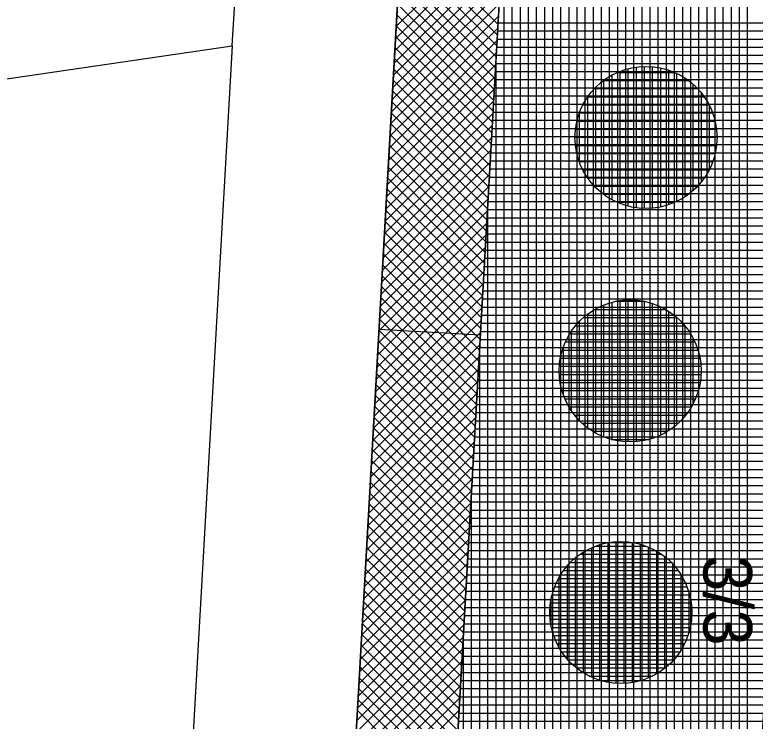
# Model space of a CAD drawing. Extents: x -565346 to -564154, y -1097386 to -1095620.
# Drawn here: x -564297.25 to -564279, y -1097000.39 to -1096982.99 of the extents above; entities that cross this region are included whole.
import ezdxf

# ---------------------------------------------------------------- set-up
doc = ezdxf.new("R2010")
doc.units = 0
for name, color, linetype in [('Vrstva 1', 7, 'Continuous'), ('Vrstva 40', 7, 'Continuous'), ('Vrstva 41', 7, 'Continuous'), ('Vrstva 42', 7, 'Continuous'), ('Vrstva 43', 7, 'Continuous'), ('Vrstva 44', 7, 'Continuous')]:
    doc.layers.add(name, color=color, linetype=linetype)

msp = doc.modelspace()

# ---------------------------------------------------------------- linework, layer by layer
at = {"layer": 'Vrstva 1'}
for p, q in [((-564296.5, -1097135.53), (-564285.9, -1096948.97)), ((-564291.89, -1096983.76), (-564290.54, -1096959.99)), ((-564455.988, -1097007.624), (-564291.89, -1096983.76)), ((-564291.89, -1096983.76), (-564296.48, -1097064.53))]:
    msp.add_line(p, q, dxfattribs=at)
at = {"layer": 'Vrstva 41'}
msp.add_line((-564288.277, -1096990.734), (-564285.782, -1096990.875), dxfattribs=at)
msp.add_lwpolyline([(-564296.782, -1097140.492), (-564294.286, -1097140.634), (-564282.373, -1096930.972), (-564284.87, -1096930.83)], close=True, dxfattribs=at)
at = {"layer": 'Vrstva 42'}
for p, q in [((-564285.194, -1096980.625), (-564287.85, -1096983.281)), ((-564285.211, -1096980.925), (-564287.867, -1096983.581)), ((-564287.712, -1096980.855), (-564285.342, -1096983.225)), ((-564287.728, -1096981.122), (-564285.357, -1096983.493)), ((-564285.228, -1096981.225), (-564287.884, -1096983.881)), ((-564285.245, -1096981.525), (-564287.901, -1096984.181)), ((-564287.743, -1096981.39), (-564285.372, -1096983.76)), ((-564287.758, -1096981.658), (-564285.388, -1096984.028)), ((-564285.262, -1096981.825), (-564287.918, -1096984.48)), ((-564287.773, -1096981.925), (-564285.403, -1096984.296)), ((-564285.279, -1096982.125), (-564287.935, -1096984.78)), ((-564287.788, -1096982.193), (-564285.418, -1096984.563)), ((-564285.297, -1096982.424), (-564287.952, -1096985.08)), ((-564287.804, -1096982.461), (-564285.433, -1096984.831)), ((-564285.314, -1096982.724), (-564287.969, -1096985.38)), ((-564287.819, -1096982.728), (-564285.448, -1096985.099)), ((-564287.834, -1096982.996), (-564285.464, -1096985.366)), ((-564285.331, -1096983.024), (-564287.986, -1096985.68)), ((-564285.348, -1096983.324), (-564288.003, -1096985.98)), ((-564287.849, -1096983.264), (-564285.479, -1096985.634)), ((-564287.864, -1096983.531), (-564285.494, -1096985.902)), ((-564285.365, -1096983.624), (-564288.021, -1096986.28)), ((-564287.88, -1096983.799), (-564285.509, -1096986.169)), ((-564285.382, -1096983.924), (-564288.038, -1096986.58)), ((-564287.895, -1096984.067), (-564285.525, -1096986.437)), ((-564285.399, -1096984.224), (-564288.055, -1096986.88)), ((-564287.91, -1096984.334), (-564285.54, -1096986.704)), ((-564285.416, -1096984.524), (-564288.072, -1096987.179)), ((-564287.925, -1096984.602), (-564285.555, -1096986.972)), ((-564285.433, -1096984.823), (-564288.089, -1096987.479)), ((-564287.94, -1096984.869), (-564285.57, -1096987.24)), ((-564285.45, -1096985.123), (-564288.106, -1096987.779)), ((-564287.956, -1096985.137), (-564285.585, -1096987.507)), ((-564285.467, -1096985.423), (-564288.123, -1096988.079)), ((-564287.971, -1096985.405), (-564285.601, -1096987.775)), ((-564285.484, -1096985.723), (-564288.14, -1096988.379)), ((-564287.986, -1096985.672), (-564285.616, -1096988.043)), ((-564285.501, -1096986.023), (-564288.157, -1096988.679)), ((-564288.001, -1096985.94), (-564285.631, -1096988.31)), ((-564288.016, -1096986.208), (-564285.646, -1096988.578)), ((-564285.518, -1096986.323), (-564288.174, -1096988.979)), ((-564285.535, -1096986.623), (-564288.191, -1096989.279)), ((-564288.032, -1096986.475), (-564285.661, -1096988.845)), ((-564288.047, -1096986.743), (-564285.677, -1096989.113)), ((-564285.552, -1096986.923), (-564288.208, -1096989.578)), ((-564288.062, -1096987.011), (-564285.692, -1096989.381)), ((-564285.569, -1096987.223), (-564288.225, -1096989.878)), ((-564288.077, -1096987.278), (-564285.707, -1096989.648)), ((-564285.586, -1096987.522), (-564288.242, -1096990.178)), ((-564288.092, -1096987.546), (-564285.722, -1096989.916)), ((-564285.603, -1096987.822), (-564288.259, -1096990.478)), ((-564288.108, -1096987.813), (-564285.737, -1096990.184)), ((-564288.123, -1096988.081), (-564285.753, -1096990.451)), ((-564285.62, -1096988.122), (-564288.276, -1096990.778)), ((-564285.637, -1096988.422), (-564288.293, -1096991.078)), ((-564288.138, -1096988.349), (-564285.768, -1096990.719)), ((-564288.153, -1096988.616), (-564285.783, -1096990.987)), ((-564285.654, -1096988.722), (-564288.31, -1096991.378)), ((-564285.671, -1096989.022), (-564288.327, -1096991.678)), ((-564288.168, -1096988.884), (-564285.798, -1096991.254)), ((-564288.184, -1096989.152), (-564285.813, -1096991.522)), ((-564285.688, -1096989.322), (-564288.344, -1096991.977)), ((-564288.199, -1096989.419), (-564285.829, -1096991.789)), ((-564285.705, -1096989.622), (-564288.361, -1096992.277)), ((-564288.214, -1096989.687), (-564285.844, -1096992.057)), ((-564285.723, -1096989.921), (-564288.378, -1096992.577)), ((-564288.229, -1096989.955), (-564285.859, -1096992.325)), ((-564285.74, -1096990.221), (-564288.395, -1096992.877)), ((-564288.244, -1096990.222), (-564285.874, -1096992.592)), ((-564285.757, -1096990.521), (-564288.412, -1096993.177)), ((-564288.26, -1096990.49), (-564285.889, -1096992.86)), ((-564285.774, -1096990.821), (-564288.429, -1096993.477)), ((-564288.275, -1096990.757), (-564285.905, -1096993.128)), ((-564288.29, -1096991.025), (-564285.92, -1096993.395)), ((-564285.791, -1096991.121), (-564288.446, -1096993.777)), ((-564288.305, -1096991.293), (-564285.935, -1096993.663)), ((-564285.808, -1096991.421), (-564288.463, -1096994.077)), ((-564288.321, -1096991.56), (-564285.95, -1096993.931)), ((-564285.825, -1096991.721), (-564288.481, -1096994.377)), ((-564288.336, -1096991.828), (-564285.966, -1096994.198)), ((-564285.842, -1096992.021), (-564288.498, -1096994.676)), ((-564288.351, -1096992.096), (-564285.981, -1096994.466)), ((-564285.859, -1096992.321), (-564288.515, -1096994.976)), ((-564288.366, -1096992.363), (-564285.996, -1096994.733)), ((-564285.876, -1096992.62), (-564288.532, -1096995.276)), ((-564288.381, -1096992.631), (-564286.011, -1096995.001)), ((-564285.893, -1096992.92), (-564288.549, -1096995.576)), ((-564288.397, -1096992.899), (-564286.026, -1096995.269)), ((-564288.412, -1096993.166), (-564286.042, -1096995.536)), ((-564285.91, -1096993.22), (-564288.566, -1096995.876)), ((-564285.927, -1096993.52), (-564288.583, -1096996.176)), ((-564288.427, -1096993.434), (-564286.057, -1096995.804)), ((-564288.442, -1096993.701), (-564286.072, -1096996.072)), ((-564285.944, -1096993.82), (-564288.6, -1096996.476)), ((-564285.961, -1096994.12), (-564288.617, -1096996.776)), ((-564288.457, -1096993.969), (-564286.087, -1096996.339)), ((-564288.473, -1096994.237), (-564286.102, -1096996.607)), ((-564285.978, -1096994.42), (-564288.634, -1096997.075)), ((-564288.488, -1096994.504), (-564286.118, -1096996.875)), ((-564285.995, -1096994.72), (-564288.651, -1096997.375)), ((-564288.503, -1096994.772), (-564286.133, -1096997.142)), ((-564286.012, -1096995.019), (-564288.668, -1096997.675)), ((-564288.518, -1096995.04), (-564286.148, -1096997.41)), ((-564286.029, -1096995.319), (-564288.685, -1096997.975)), ((-564288.533, -1096995.307), (-564286.163, -1096997.677)), ((-564288.549, -1096995.575), (-564286.178, -1096997.945)), ((-564286.046, -1096995.619), (-564288.702, -1096998.275)), ((-564286.063, -1096995.919), (-564288.719, -1096998.575)), ((-564288.564, -1096995.843), (-564286.194, -1096998.213)), ((-564288.579, -1096996.11), (-564286.209, -1096998.48)), ((-564286.08, -1096996.219), (-564288.736, -1096998.875)), ((-564288.594, -1096996.378), (-564286.224, -1096998.748)), ((-564286.097, -1096996.519), (-564288.753, -1096999.175)), ((-564288.609, -1096996.645), (-564286.239, -1096999.016)), ((-564286.114, -1096996.819), (-564288.77, -1096999.474)), ((-564288.625, -1096996.913), (-564286.254, -1096999.283)), ((-564286.131, -1096997.119), (-564288.787, -1096999.774)), ((-564288.64, -1096997.181), (-564286.27, -1096999.551)), ((-564286.148, -1096997.419), (-564288.804, -1097000.074)), ((-564288.655, -1096997.448), (-564286.285, -1096999.819)), ((-564286.166, -1096997.718), (-564288.821, -1097000.374)), ((-564288.67, -1096997.716), (-564286.3, -1097000.086)), ((-564286.183, -1096998.018), (-564288.838, -1097000.674)), ((-564288.685, -1096997.984), (-564286.315, -1097000.354)), ((-564286.2, -1096998.318), (-564288.855, -1097000.974)), ((-564288.701, -1096998.251), (-564286.33, -1097000.621)), ((-564286.217, -1096998.618), (-564288.872, -1097001.274)), ((-564288.716, -1096998.519), (-564286.346, -1097000.889)), ((-564288.731, -1096998.787), (-564286.361, -1097001.157)), ((-564286.234, -1096998.918), (-564288.889, -1097001.574)), ((-564288.746, -1096999.054), (-564286.376, -1097001.424)), ((-564286.251, -1096999.218), (-564288.906, -1097001.874)), ((-564288.761, -1096999.322), (-564286.391, -1097001.692)), ((-564286.268, -1096999.518), (-564288.923, -1097002.173)), ((-564288.777, -1096999.589), (-564286.407, -1097001.96)), ((-564286.285, -1096999.818), (-564288.941, -1097002.473)), ((-564288.792, -1096999.857), (-564286.422, -1097002.227)), ((-564286.302, -1097000.117), (-564288.958, -1097002.773)), ((-564288.807, -1097000.125), (-564286.437, -1097002.495))]:
    msp.add_line(p, q, dxfattribs=at)
at = {"layer": 'Vrstva 43'}
for p, q in [((-564279.19, -1097007.173), (-564279.19, -1096883.64)), ((-564279.39, -1097010.696), (-564279.39, -1096887.165)), ((-564279.59, -1097014.219), (-564279.59, -1096890.689)), ((-564279.79, -1097017.742), (-564279.79, -1096894.214)), ((-564279.99, -1097021.265), (-564279.99, -1096897.739)), ((-564280.19, -1097024.788), (-564280.19, -1096901.264)), ((-564280.39, -1097028.31), (-564280.39, -1096904.789)), ((-564282.19, -1097060.016), (-564282.19, -1096906.123)), ((-564281.99, -1097056.493), (-564281.99, -1096906.114)), ((-564281.79, -1097052.97), (-564281.79, -1096906.104)), ((-564281.59, -1097049.447), (-564281.59, -1096906.094)), ((-564281.39, -1097045.925), (-564281.39, -1096906.085)), ((-564281.19, -1097042.402), (-564281.19, -1096906.075)), ((-564280.99, -1097038.879), (-564280.99, -1096906.065)), ((-564280.79, -1097035.356), (-564280.79, -1096906.056)), ((-564280.59, -1097031.833), (-564280.59, -1096906.046)), ((-564282.39, -1097063.539), (-564282.39, -1096931.271)), ((-564282.59, -1097067.062), (-564282.59, -1096934.791)), ((-564282.79, -1097070.585), (-564282.79, -1096938.311)), ((-564282.99, -1097074.107), (-564282.99, -1096941.831)), ((-564283.19, -1097077.63), (-564283.19, -1096945.351)), ((-564283.39, -1097081.153), (-564283.39, -1096948.871)), ((-564283.59, -1097084.676), (-564283.59, -1096952.391)), ((-564283.79, -1097088.199), (-564283.79, -1096955.91)), ((-564283.99, -1097091.722), (-564283.99, -1096959.43)), ((-564284.19, -1097095.244), (-564284.19, -1096962.95)), ((-564284.39, -1097098.767), (-564284.39, -1096966.47)), ((-564284.59, -1097102.29), (-564284.59, -1096969.99)), ((-564284.79, -1097105.813), (-564284.79, -1096973.51)), ((-564284.99, -1097109.336), (-564284.99, -1096977.03)), ((-564285.19, -1097112.859), (-564285.19, -1096980.55)), ((-564285.34, -1096983.19), (-564277.828, -1096983.19)), ((-564285.351, -1096983.39), (-564277.84, -1096983.39)), ((-564285.363, -1096983.59), (-564277.851, -1096983.59)), ((-564285.374, -1096983.79), (-564277.862, -1096983.79)), ((-564285.39, -1097116.382), (-564285.39, -1096984.069)), ((-564285.385, -1096983.99), (-564277.874, -1096983.99)), ((-564285.397, -1096984.19), (-564277.885, -1096984.19)), ((-564285.408, -1096984.39), (-564277.897, -1096984.39)), ((-564285.42, -1096984.59), (-564277.908, -1096984.59)), ((-564285.431, -1096984.79), (-564277.919, -1096984.79)), ((-564285.442, -1096984.99), (-564277.931, -1096984.99)), ((-564285.454, -1096985.19), (-564277.942, -1096985.19)), ((-564285.465, -1096985.39), (-564277.953, -1096985.39)), ((-564285.476, -1096985.59), (-564277.965, -1096985.59)), ((-564285.488, -1096985.79), (-564277.976, -1096985.79)), ((-564285.499, -1096985.99), (-564277.987, -1096985.99)), ((-564285.51, -1096986.19), (-564277.999, -1096986.19)), ((-564285.522, -1096986.39), (-564278.01, -1096986.39)), ((-564285.533, -1096986.59), (-564278.021, -1096986.59)), ((-564285.545, -1096986.79), (-564278.033, -1096986.79)), ((-564285.556, -1096986.99), (-564278.044, -1096986.99)), ((-564285.567, -1096987.19), (-564278.055, -1096987.19)), ((-564285.579, -1096987.39), (-564278.067, -1096987.39)), ((-564285.59, -1097119.904), (-564285.59, -1096987.589)), ((-564285.59, -1096987.59), (-564278.078, -1096987.59)), ((-564285.601, -1096987.79), (-564278.09, -1096987.79)), ((-564285.613, -1096987.99), (-564278.101, -1096987.99)), ((-564285.624, -1096988.19), (-564278.112, -1096988.19)), ((-564285.635, -1096988.39), (-564278.124, -1096988.39)), ((-564285.647, -1096988.59), (-564278.135, -1096988.59)), ((-564285.658, -1096988.79), (-564278.146, -1096988.79)), ((-564285.67, -1096988.99), (-564278.158, -1096988.99)), ((-564285.681, -1096989.19), (-564278.169, -1096989.19)), ((-564285.692, -1096989.39), (-564278.18, -1096989.39)), ((-564285.704, -1096989.59), (-564278.192, -1096989.59)), ((-564285.715, -1096989.79), (-564278.203, -1096989.79)), ((-564285.726, -1096989.99), (-564278.214, -1096989.99)), ((-564285.738, -1096990.19), (-564278.226, -1096990.19)), ((-564285.749, -1096990.39), (-564278.237, -1096990.39)), ((-564285.76, -1096990.59), (-564278.249, -1096990.59)), ((-564285.772, -1096990.79), (-564278.26, -1096990.79)), ((-564285.783, -1096990.99), (-564278.271, -1096990.99)), ((-564285.795, -1096991.19), (-564278.283, -1096991.19)), ((-564285.79, -1097123.427), (-564285.79, -1096991.109)), ((-564285.806, -1096991.39), (-564278.294, -1096991.39)), ((-564285.817, -1096991.59), (-564278.305, -1096991.59)), ((-564285.829, -1096991.79), (-564278.317, -1096991.79)), ((-564285.84, -1096991.99), (-564278.328, -1096991.99)), ((-564285.851, -1096992.19), (-564278.339, -1096992.19)), ((-564285.863, -1096992.39), (-564278.351, -1096992.39)), ((-564285.874, -1096992.59), (-564278.362, -1096992.59)), ((-564285.885, -1096992.79), (-564278.373, -1096992.79)), ((-564285.897, -1096992.99), (-564278.385, -1096992.99)), ((-564285.908, -1096993.19), (-564278.396, -1096993.19)), ((-564285.92, -1096993.39), (-564278.407, -1096993.39)), ((-564285.931, -1096993.59), (-564278.419, -1096993.59)), ((-564285.942, -1096993.79), (-564278.43, -1096993.79)), ((-564285.954, -1096993.99), (-564278.442, -1096993.99)), ((-564285.965, -1096994.19), (-564278.453, -1096994.19)), ((-564285.976, -1096994.39), (-564278.464, -1096994.39)), ((-564285.99, -1097126.95), (-564285.99, -1096994.629)), ((-564285.988, -1096994.59), (-564278.476, -1096994.59)), ((-564285.999, -1096994.79), (-564278.487, -1096994.79)), ((-564286.011, -1096994.99), (-564278.498, -1096994.99)), ((-564286.022, -1096995.19), (-564278.51, -1096995.19)), ((-564286.033, -1096995.39), (-564278.521, -1096995.39)), ((-564286.045, -1096995.59), (-564278.532, -1096995.59)), ((-564286.056, -1096995.79), (-564278.544, -1096995.79)), ((-564286.067, -1096995.99), (-564278.555, -1096995.99)), ((-564286.079, -1096996.19), (-564278.566, -1096996.19)), ((-564286.09, -1096996.39), (-564278.578, -1096996.39)), ((-564286.101, -1096996.59), (-564278.589, -1096996.59)), ((-564286.113, -1096996.79), (-564278.601, -1096996.79)), ((-564286.124, -1096996.99), (-564278.612, -1096996.99)), ((-564286.136, -1096997.19), (-564278.623, -1096997.19)), ((-564286.147, -1096997.39), (-564278.635, -1096997.39)), ((-564286.158, -1096997.59), (-564278.646, -1096997.59)), ((-564286.17, -1096997.79), (-564278.657, -1096997.79)), ((-564286.181, -1096997.99), (-564278.669, -1096997.99)), ((-564286.192, -1096998.19), (-564278.68, -1096998.19)), ((-564286.19, -1097130.473), (-564286.19, -1096998.149)), ((-564286.204, -1096998.39), (-564278.691, -1096998.39)), ((-564286.215, -1096998.59), (-564278.703, -1096998.59)), ((-564286.226, -1096998.79), (-564278.714, -1096998.79)), ((-564286.238, -1096998.99), (-564278.725, -1096998.99)), ((-564286.249, -1096999.19), (-564278.737, -1096999.19)), ((-564286.261, -1096999.39), (-564278.748, -1096999.39)), ((-564286.272, -1096999.59), (-564278.759, -1096999.59)), ((-564286.283, -1096999.79), (-564278.771, -1096999.79)), ((-564286.295, -1096999.99), (-564278.782, -1096999.99)), ((-564286.306, -1097000.19), (-564278.794, -1097000.19)), ((-564286.317, -1097000.39), (-564278.805, -1097000.39))]:
    msp.add_line(p, q, dxfattribs=at)
msp.add_lwpolyline([(-564283.37, -1096906.18), (-564284.87, -1096930.83), (-564282.373, -1096930.972), (-564294.286, -1097140.634), (-564296.782, -1097140.492), (-564297.42, -1097150.37), (-564294.347, -1097150.646), (-564303.226, -1097307.04), (-564304.096, -1097322.37), (-564304.399, -1097332.838), (-564302.848, -1097333.175), (-564297.082, -1097322.329), (-564293.197, -1097253.877), (-564289.027, -1097180.417), (-564287.358, -1097151.043), (-564285.364, -1097151.156), (-564284.798, -1097141.172), (-564286.791, -1097141.059), (-564274.888, -1096931.397), (-564272.899, -1096931.51), (-564271.475, -1096906.55)], dxfattribs=at)
at = {"layer": 'Vrstva 44'}
for p, q in [((-564281.73, -1096987.763), (-564281.73, -1096984.266)), ((-564281.53, -1096987.755), (-564281.53, -1096984.273)), ((-564282.389, -1096984.41), (-564280.997, -1096984.41)), ((-564282.33, -1096987.644), (-564282.33, -1096984.384)), ((-564282.13, -1096987.708), (-564282.13, -1096984.321)), ((-564281.93, -1096987.747), (-564281.93, -1096984.282)), ((-564281.33, -1096987.724), (-564281.33, -1096984.303)), ((-564281.13, -1096987.669), (-564281.13, -1096984.359)), ((-564280.93, -1096987.588), (-564280.93, -1096984.442)), ((-564282.737, -1096984.61), (-564280.653, -1096984.61)), ((-564282.73, -1096987.422), (-564282.73, -1096984.605)), ((-564282.53, -1096987.55), (-564282.53, -1096984.479)), ((-564280.73, -1096987.472), (-564280.73, -1096984.554)), ((-564282.962, -1096984.81), (-564280.427, -1096984.81)), ((-564282.93, -1096987.251), (-564282.93, -1096984.778)), ((-564280.53, -1096987.32), (-564280.53, -1096984.71)), ((-564280.33, -1096987.107), (-564280.33, -1096984.92)), ((-564283.13, -1096987.014), (-564283.13, -1096985.016)), ((-564283.126, -1096985.01), (-564280.262, -1096985.01)), ((-564283.246, -1096985.21), (-564280.142, -1096985.21)), ((-564280.13, -1096986.797), (-564280.13, -1096985.234)), ((-564283.336, -1096985.41), (-564280.054, -1096985.41)), ((-564283.33, -1096986.631), (-564283.33, -1096985.396)), ((-564283.396, -1096985.61), (-564279.993, -1096985.61)), ((-564283.43, -1096985.81), (-564279.957, -1096985.81)), ((-564283.442, -1096986.01), (-564279.946, -1096986.01)), ((-564283.432, -1096986.21), (-564279.957, -1096986.21)), ((-564283.398, -1096986.41), (-564279.991, -1096986.41)), ((-564283.338, -1096986.61), (-564280.049, -1096986.61)), ((-564283.25, -1096986.81), (-564280.137, -1096986.81)), ((-564283.132, -1096987.01), (-564280.258, -1096987.01)), ((-564282.969, -1096987.21), (-564280.418, -1096987.21)), ((-564282.747, -1096987.41), (-564280.64, -1096987.41)), ((-564282.407, -1096987.61), (-564280.98, -1096987.61)), ((-564282.53, -1096993.455), (-564282.53, -1096990.073)), ((-564282.43, -1096990.05), (-564281.732, -1096990.05)), ((-564282.33, -1096993.495), (-564282.33, -1096990.033)), ((-564282.13, -1096993.513), (-564282.13, -1096990.017)), ((-564281.93, -1096993.506), (-564281.93, -1096990.022)), ((-564281.73, -1096993.476), (-564281.73, -1096990.05)), ((-564281.53, -1096993.422), (-564281.53, -1096990.106)), ((-564282.958, -1096990.25), (-564281.21, -1096990.25)), ((-564282.93, -1096993.294), (-564282.93, -1096990.234)), ((-564282.73, -1096993.39), (-564282.73, -1096990.138)), ((-564281.33, -1096993.343), (-564281.33, -1096990.187)), ((-564281.13, -1096993.229), (-564281.13, -1096990.298)), ((-564283.237, -1096990.45), (-564280.931, -1096990.45)), ((-564283.13, -1096993.165), (-564283.13, -1096990.362)), ((-564280.93, -1096993.078), (-564280.93, -1096990.451)), ((-564283.431, -1096990.65), (-564280.735, -1096990.65)), ((-564283.33, -1096992.991), (-564283.33, -1096990.538)), ((-564280.73, -1096992.869), (-564280.73, -1096990.657)), ((-564283.53, -1096992.748), (-564283.53, -1096990.781)), ((-564283.575, -1096990.85), (-564280.594, -1096990.85)), ((-564280.53, -1096992.565), (-564280.53, -1096990.963)), ((-564283.73, -1096992.355), (-564283.73, -1096991.17)), ((-564283.681, -1096991.05), (-564280.487, -1096991.05)), ((-564283.755, -1096991.25), (-564280.412, -1096991.25)), ((-564283.804, -1096991.45), (-564280.365, -1096991.45)), ((-564283.83, -1096991.65), (-564280.34, -1096991.65)), ((-564283.831, -1096991.85), (-564280.338, -1096991.85)), ((-564283.809, -1096992.05), (-564280.358, -1096992.05)), ((-564283.763, -1096992.25), (-564280.404, -1096992.25)), ((-564283.693, -1096992.45), (-564280.476, -1096992.45)), ((-564283.592, -1096992.65), (-564280.576, -1096992.65)), ((-564283.454, -1096992.85), (-564280.714, -1096992.85)), ((-564283.269, -1096993.05), (-564280.898, -1096993.05)), ((-564283.006, -1096993.25), (-564281.161, -1096993.25)), ((-564282.55, -1096993.45), (-564281.618, -1096993.45)), ((-564283.03, -1096999.309), (-564283.03, -1096996.119)), ((-564282.94, -1096996.08), (-564281.693, -1096996.08)), ((-564282.83, -1096999.385), (-564282.83, -1096996.043)), ((-564282.63, -1096999.433), (-564282.63, -1096995.993)), ((-564282.43, -1096999.458), (-564282.43, -1096995.969)), ((-564282.23, -1096999.461), (-564282.23, -1096995.968)), ((-564282.03, -1096999.441), (-564282.03, -1096995.989)), ((-564281.83, -1096999.394), (-564281.83, -1096996.034)), ((-564281.63, -1096999.323), (-564281.63, -1096996.104)), ((-564283.314, -1096996.28), (-564281.314, -1096996.28)), ((-564283.23, -1096999.204), (-564283.23, -1096996.224)), ((-564281.43, -1096999.223), (-564281.43, -1096996.206)), ((-564283.552, -1096996.48), (-564281.074, -1096996.48)), ((-564283.43, -1096999.06), (-564283.43, -1096996.368)), ((-564281.23, -1096999.086), (-564281.23, -1096996.342)), ((-564283.726, -1096996.68), (-564280.905, -1096996.68)), ((-564283.63, -1096998.867), (-564283.63, -1096996.561)), ((-564281.03, -1096998.902), (-564281.03, -1096996.528)), ((-564283.83, -1096998.588), (-564283.83, -1096996.841)), ((-564280.83, -1096998.64), (-564280.83, -1096996.791)), ((-564283.851, -1096996.88), (-564280.776, -1096996.88)), ((-564283.943, -1096997.08), (-564280.685, -1096997.08)), ((-564284.03, -1096998.048), (-564284.03, -1096997.38)), ((-564284.009, -1096997.28), (-564280.621, -1096997.28)), ((-564280.63, -1096998.186), (-564280.63, -1096997.246)), ((-564284.047, -1096997.48), (-564280.581, -1096997.48)), ((-564284.062, -1096997.68), (-564280.565, -1096997.68)), ((-564284.054, -1096997.88), (-564280.574, -1096997.88)), ((-564284.024, -1096998.08), (-564280.605, -1096998.08)), ((-564283.97, -1096998.28), (-564280.66, -1096998.28)), ((-564283.886, -1096998.48), (-564280.741, -1096998.48)), ((-564283.771, -1096998.68), (-564280.857, -1096998.68)), ((-564283.617, -1096998.88), (-564281.01, -1096998.88)), ((-564283.407, -1096999.08), (-564281.223, -1096999.08)), ((-564283.093, -1096999.28), (-564281.535, -1096999.28))]:
    msp.add_line(p, q, dxfattribs=at)
for centre in [(-564281.694, -1096986.014), (-564282.084, -1096991.764), (-564282.314, -1096997.714)]:
    msp.add_circle(centre, 1.75, dxfattribs=at)

# ---------------------------------------------------------------- texts
at = {"layer": 'Vrstva 40'}
msp.add_text('3/3', height=1.2, rotation=270, dxfattribs=at).set_placement((-564280.28, -1096996.3))

doc.saveas('drawing.dxf')
